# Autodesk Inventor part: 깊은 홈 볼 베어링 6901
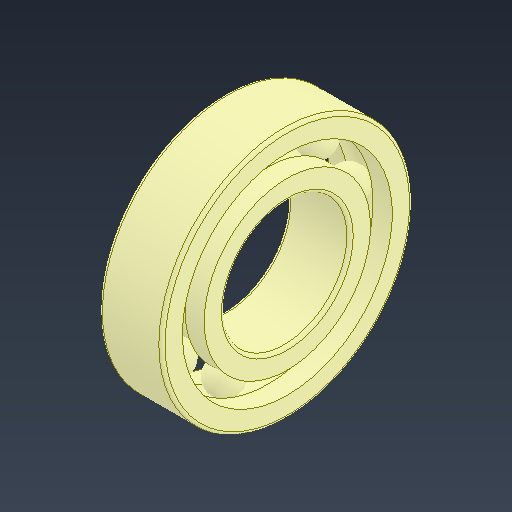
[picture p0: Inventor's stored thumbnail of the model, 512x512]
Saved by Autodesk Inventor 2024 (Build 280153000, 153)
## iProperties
Created: 2024-05
Part Number: 깊은 홈 볼 베어링 6901
Material: 강철, 연강
Description: 깊은 그루브 볼 베어링
Document SubType Name: Modeling
Designer: kh_501
Density: 7.85 g/cm^3
Appearance: 기본값
Author: jhkim
Sending System: Autodesk Inventor 2025
Preprocessor: ST-DEVELOPER v20
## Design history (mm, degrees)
node "깊은 홈 볼 베어링 69011"
node "솔리드1"
node "솔리드2"
node "솔리드3"
node "솔리드4"
node "솔리드5"
node "솔리드6"
node "솔리드7"
node "솔리드8"
node "솔리드9"
node "솔리드10"
node "솔리드11"
body "Solid1"
node "Solid1:1"
node "Solid1:2"
node "Solid1:3"
node "Solid1:4"
node "Solid1:5"
node "Solid1:6"
node "Solid1:7"
node "Solid1:8"
node "Solid1:9"
node "Solid1:10"
